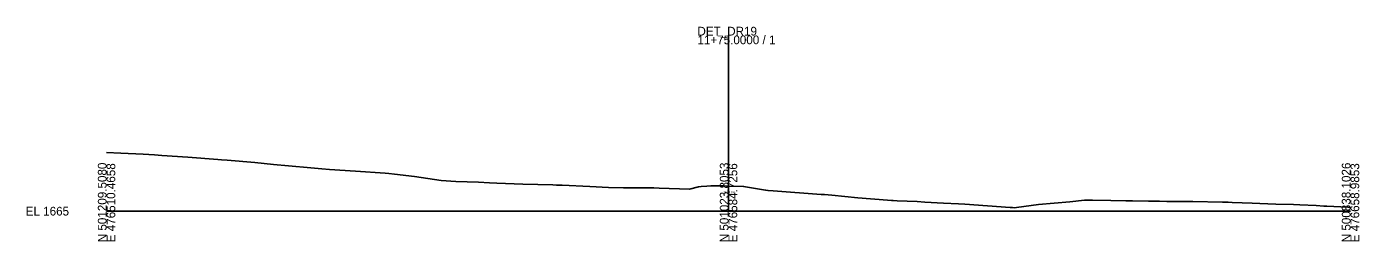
# Model space of a CAD drawing. Extents: x -26 to 403, y -10 to 3059.
# Drawn here: x -25.7 to 402.8, y 2990.3 to 3059.3 of the extents above; entities that cross this region are included whole.
import ezdxf

# ---------------------------------------------------------------- set-up
doc = ezdxf.new("R2010")
doc.units = 0
for name, color, linetype in [('Exist Cross Section Cell', 7, 'Continuous'), ('Exist XS Center Line Elevation Label', 7, 'Continuous'), ('Exist XS Ground Line', 7, 'Continuous')]:
    doc.layers.add(name, color=color, linetype=linetype)

msp = doc.modelspace()

# ---------------------------------------------------------------- linework, layer by layer
at = {"layer": 'Exist Cross Section Cell'}
for p, q in [((200, 3000), (200, 3056.45)), ((0, 3000), (200, 3000)), ((200, 3000), (400, 3000))]:
    msp.add_line(p, q, dxfattribs=at)
at = {"layer": 'Exist XS Ground Line'}
msp.add_lwpolyline([(0, 3018.82), (4.63, 3018.61), (11.8, 3018.3), (15.4, 3018.15), (17.81, 3017.94), (26.17, 3017.35), (35.76, 3016.57), (36.95, 3016.48), (38.74, 3016.34), (47.72, 3015.6), (53.71, 3015.03), (58.49, 3014.57), (65.67, 3013.9), (69.26, 3013.58), (71.66, 3013.42), (80.03, 3012.82), (89.61, 3012.25), (90.81, 3012.14), (92.61, 3011.93), (99.02, 3011.1), (107.56, 3009.88), (112.35, 3009.56), (119.55, 3009.28), (123.12, 3009.16), (125.5, 3009.04), (133.89, 3008.63), (143.45, 3008.45), (144.67, 3008.41), (146.49, 3008.32), (155.44, 3007.9), (161.4, 3007.65), (166.21, 3007.52), (173.42, 3007.48), (175.97, 3007.47), (177.74, 3007.41), (187.41, 3007.11), (190.34, 3007.87), (191.19, 3007.95), (192.99, 3008.05), (194.31, 3008.14), (198.39, 3008.1), (200, 3008.06), (204.85, 3007.96), (211.91, 3006.76), (212.71, 3006.62), (214.4, 3006.56), (229.83, 3005.4), (230.84, 3005.34), (233.2, 3005.1), (241.61, 3004.33), (251.15, 3003.55), (252.39, 3003.43), (252.92, 3003.39), (254.24, 3003.33), (260.61, 3003.06), (263.16, 3002.88), (269.1, 3002.59), (273.93, 3002.32), (276, 3002.22), (290.56, 3001.2), (291.33, 3001.17), (292.1, 3001.08), (292.63, 3001.23), (299.72, 3002.14), (309.79, 3002.98), (314.47, 3003.55), (317.02, 3003.51), (322.95, 3003.42), (327.79, 3003.35), (329.86, 3003.3), (335.05, 3003.24), (337.56, 3003.2), (338.56, 3003.18), (340.9, 3003.16), (349.33, 3003.08), (358.85, 3002.88), (360.11, 3002.86), (360.64, 3002.85), (361.99, 3002.81), (368.34, 3002.6), (370.88, 3002.5), (376.03, 3002.23), (381.65, 3002.12), (383.73, 3002), (388.93, 3001.78), (391.42, 3001.63), (392.42, 3001.6), (399.12, 3001.25), (400, 3001.22)], dxfattribs=at)

# ---------------------------------------------------------------- texts
at = {"layer": 'Exist Cross Section Cell'}
for s, p in [('11+75.0000 / 1', (190, 3053.65)), ('DET_DR19', (190, 3056.45)), ('EL 1665', (-26, 2998.6))]:
    msp.add_text(s, height=2.8, dxfattribs=at).set_placement(p)
for s, p in [('N 501209.5080', (0, 2990)), ('E 476510.4658', (2.8, 2990)), ('N 501023.8053', (200, 2990)), ('E 476584.7256', (202.8, 2990)), ('N 500838.1026', (400, 2990)), ('E 476658.9853', (402.8, 2990))]:
    msp.add_text(s, height=2.8, rotation=90, dxfattribs=at).set_placement(p)
at = {"layer": 'Exist XS Center Line Elevation Label'}
msp.add_text('1673.06', height=0.75, dxfattribs=at).set_placement((198.26, 3005.69))

doc.saveas('drawing.dxf')
